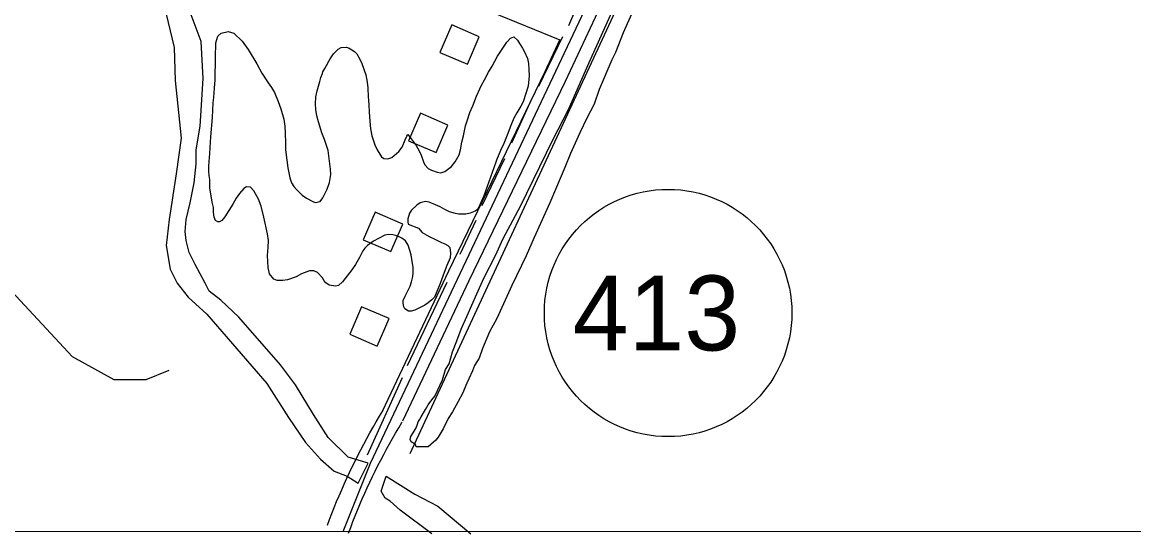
# Model space of a CAD drawing. Extents: x 3250478 to 3288318, y 788638 to 816472.
# Drawn here: x 3257033 to 3258515, y 794014 to 794702 of the extents above; entities that cross this region are included whole.
import ezdxf

# ---------------------------------------------------------------- set-up
doc = ezdxf.new("R2010")
doc.units = 0
for name, color, linetype in [('V-BLDG-OTLN', 7, 'Continuous'), ('V-GRID-FRAM', 7, 'Continuous'), ('V-ROAD-CNTR', 7, 'Continuous'), ('V-ROAD-IDEN', 7, 'Continuous'), ('V-SITE-VEGE', 7, 'Continuous'), ('V-TOPO-SHOR', 7, 'Continuous')]:
    doc.layers.add(name, color=color, linetype=linetype)

msp = doc.modelspace()

# ---------------------------------------------------------------- linework, layer by layer
at = {"layer": 'V-BLDG-OTLN'}
for points in [[(3257626.5, 794645.3), (3257642.3, 794682), (3257605.6, 794697.9), (3257589.8, 794661.2)], [(3257584.7, 794527.6), (3257600.6, 794564.3), (3257563.9, 794580.2), (3257548, 794543.4)], [(3257524.4, 794395.4), (3257540.3, 794432.1), (3257503.6, 794447.9), (3257487.7, 794411.2)], [(3257506.3, 794269.3), (3257522.2, 794306), (3257485.5, 794321.9), (3257469.6, 794285.2)]]:
    msp.add_lwpolyline(points, close=True, dxfattribs=at)
at = {"layer": 'V-GRID-FRAM'}
msp.add_lwpolyline([(3254649.6, 812209.1), (3286070.1, 812200), (3286072.7, 794013.5), (3254636.4, 794022.7), (3254649.6, 812209.1)], dxfattribs=at)
at = {"layer": 'V-ROAD-CNTR'}
for points in [[(3257460.7, 794021.9), (3257497.3, 794112.9), (3257860.4, 794882.3), (3257924.8, 795086.6), (3257932, 795269.1), (3257930.7, 796474.2), (3257808.6, 796519), (3257044, 796867.7), (3256342, 797271.9), (3255916.7, 797438.8), (3254738.6, 797696.6), (3254639.1, 797722.8)], [(3257540.5, 794169.6), (3257629, 794356.8), (3257757.1, 794622.8), (3257857.1, 794837), (3257911.9, 794967)], [(3257292.2, 794865.1), (3257749.7, 794677.9)], [(3257513.4, 794182.5), (3257601.9, 794369.7), (3257730, 794635.6), (3257749.7, 794677.9)], [(3257439.9, 794030.2), (3257442.8, 794038.1), (3257445.9, 794046), (3257449, 794053.9), (3257452.2, 794061.8), (3257455.5, 794069.6), (3257458.9, 794077.4), (3257462.3, 794085.2), (3257465.8, 794092.9), (3257469.4, 794100.6), (3257473, 794108.3), (3257476.8, 794115.9), (3257480.6, 794123.5), (3257484.4, 794131.1), (3257488.4, 794138.6), (3257492.4, 794146.1), (3257496.5, 794153.6), (3257500.7, 794161), (3257504.9, 794168.3), (3257509.2, 794175.7), (3257513.6, 794182.9), (3257514.1, 794183.8)], [(3257468, 794019.7), (3257470.9, 794027.4), (3257473.8, 794035.1), (3257476.9, 794042.7), (3257480, 794050.3), (3257483.1, 794057.9), (3257486.4, 794065.4), (3257489.7, 794072.9), (3257493.1, 794080.4), (3257496.5, 794087.9), (3257500.1, 794095.3), (3257503.7, 794102.6), (3257507.3, 794110), (3257511.1, 794117.3), (3257514.9, 794124.6), (3257518.8, 794131.8), (3257522.7, 794139), (3257526.8, 794146.1), (3257530.8, 794153.3), (3257535, 794160.3), (3257539.2, 794167.4), (3257539.7, 794168.2)]]:
    msp.add_lwpolyline(points, dxfattribs=at)
at = {"layer": 'V-ROAD-IDEN'}
msp.add_circle((3257894.1, 794313.5), 165, dxfattribs=at)
at = {"layer": 'V-SITE-VEGE'}
for points in [[(3257858.2, 794741.4), (3257834.4, 794687.4), (3257824, 794660.9), (3257819.2, 794651.1), (3257802.1, 794611.8), (3257795.4, 794592.1), (3257785.9, 794573.5), (3257776.3, 794553.8), (3257764, 794526.3), (3257756.3, 794507.6), (3257744, 794478.2), (3257736.4, 794460.5), (3257724, 794433), (3257715.4, 794414.3), (3257704.9, 794389.7), (3257685.8, 794350.4), (3257665.8, 794306.2), (3257656.2, 794288.5), (3257646.7, 794265.9), (3257642, 794253.2), (3257636.2, 794243.3), (3257633.4, 794236.4), (3257628.6, 794225.6), (3257625.8, 794219.7), (3257620.1, 794206), (3257614.3, 794195.2), (3257606.7, 794181.4), (3257600.9, 794172.5), (3257594.2, 794158.8), (3257587.5, 794147.9), (3257584.6, 794144), (3257577.8, 794138.1), (3257574, 794135.1), (3257558.3, 794134.9), (3257557.3, 794137.8), (3257551.4, 794141.7), (3257550.4, 794144.6), (3257551.3, 794148.5), (3257554.2, 794153.4), (3257558, 794160.3), (3257559.9, 794165.2)], [(3257559.9, 794165.2), (3257560.9, 794168.2), (3257562.8, 794171.1), (3257564.7, 794175), (3257570.5, 794184.9), (3257574.3, 794190.8), (3257579.1, 794197.7), (3257583, 794202.6), (3257593.5, 794224.2), (3257597.2, 794238), (3257602, 794245.8), (3257606.7, 794261.5), (3257612.4, 794276.3), (3257618.1, 794292), (3257625.7, 794308.7), (3257639, 794339.1), (3257648.6, 794359.8), (3257663.9, 794390.2), (3257674.4, 794412.8), (3257697.3, 794456.1), (3257740.3, 794544.6), (3257761.3, 794584.9), (3257788.9, 794647.8), (3257829.9, 794739.1)], [(3257287.9, 794454.3), (3257286.2, 794461.5), (3257283.3, 794480.4), (3257282.9, 794491.5), (3257282.3, 794497.1), (3257281.9, 794502.2), (3257281.9, 794509.5), (3257282.1, 794515.5), (3257283.3, 794526.3), (3257283.5, 794534.4), (3257284.4, 794548.7), (3257286.8, 794574.4), (3257287.6, 794593.9), (3257288.4, 794600.9), (3257289.3, 794613.3), (3257290, 794624.4), (3257290.5, 794654.6), (3257291.3, 794673.8), (3257293.9, 794683), (3257298.2, 794686.9), (3257307.6, 794689.1), (3257314.9, 794687.1), (3257326.4, 794676.1), (3257334.3, 794665.1), (3257345.6, 794645.8), (3257352.5, 794633.5), (3257361.1, 794620.4), (3257365.4, 794614.2), (3257369.3, 794607.8), (3257374, 794595.7), (3257377.7, 794585.7), (3257381.6, 794572), (3257383, 794562.8), (3257383.7, 794553.4), (3257383.9, 794540.2), (3257384.2, 794531.2), (3257385.7, 794517.2), (3257386.9, 794507.2), (3257389.8, 794493.8), (3257391.8, 794487.3), (3257395.1, 794482.2), (3257398.6, 794478.2), (3257406, 794470.7), (3257412.2, 794466.8), (3257421.5, 794461.7), (3257424.2, 794461), (3257430.1, 794462.4), (3257433.8, 794467), (3257439.6, 794478.7), (3257442.8, 794487.6), (3257444.3, 794498.5), (3257444.2, 794505.2), (3257440.9, 794530.3), (3257436.2, 794544.8), (3257432.6, 794553.9), (3257428.1, 794568.5), (3257425.8, 794576.5)], [(3257425.8, 794576.5), (3257424.6, 794584.9), (3257424, 794592.2), (3257424.5, 794601.9), (3257426.2, 794610), (3257429.9, 794622.2), (3257430.9, 794627.6), (3257433.3, 794633.1), (3257433.8, 794635.2), (3257436.4, 794639.9), (3257438.8, 794643.7), (3257441.7, 794649.6), (3257443.6, 794652.6), (3257448.1, 794659.4), (3257454.2, 794665.4), (3257458.3, 794667.7), (3257465.3, 794668.3), (3257469.1, 794666.7), (3257475.9, 794662.5), (3257479.1, 794659.3), (3257483.3, 794652), (3257485.8, 794646.4), (3257491.3, 794631.3), (3257492.8, 794621.6), (3257493.7, 794613.8), (3257494.1, 794601.4), (3257494.7, 794597.9), (3257496.1, 794574.7), (3257497.3, 794559.3), (3257499.3, 794549.9), (3257503, 794538), (3257506, 794531), (3257512.1, 794521.9), (3257515.1, 794519.8), (3257520.5, 794519), (3257525.8, 794521), (3257535.2, 794528.9), (3257539.7, 794534.9), (3257543.4, 794544.4), (3257545.8, 794549.6), (3257547.1, 794551.5), (3257551.5, 794545.9), (3257558.1, 794537), (3257561.6, 794530.6), (3257564.7, 794523.9), (3257567.8, 794515), (3257569.7, 794511.2), (3257574.3, 794506.4), (3257578.7, 794504.1), (3257586, 794501.4), (3257591.1, 794500.7), (3257596.5, 794502.4), (3257605.4, 794509), (3257610.2, 794515.2), (3257615.7, 794524.7), (3257617.5, 794531), (3257619.3, 794541.5), (3257621.4, 794549.9), (3257624.2, 794563.2), (3257626, 794569.9), (3257629.9, 794581.1), (3257633.9, 794590), (3257638.8, 794603), (3257645.2, 794617.4), (3257649.4, 794624.8), (3257654.7, 794634.8), (3257659.4, 794643), (3257666.6, 794656), (3257671.9, 794664.4), (3257679.1, 794675.1), (3257683.9, 794680.2), (3257688.4, 794681.9), (3257693.1, 794677.7), (3257695.8, 794673.1), (3257700.2, 794666.9), (3257702.7, 794662.1), (3257706.8, 794653.2), (3257708, 794646.5), (3257708.4, 794638.4), (3257709, 794630), (3257707.5, 794616), (3257701, 794595.4), (3257697.6, 794589.4), (3257692.3, 794580.7), (3257688.6, 794573.6), (3257683.6, 794561.4), (3257680.5, 794553), (3257675, 794539.5), (3257670.5, 794530.5), (3257665.2, 794517.2), (3257664.2, 794513.4), (3257648.5, 794469.8), (3257641.4, 794453.7), (3257640, 794451.8), (3257636.8, 794449.4), (3257630.1, 794446.6), (3257624.5, 794445.4), (3257615.3, 794445.3), (3257610.7, 794446.4), (3257602.5, 794448.7), (3257596.3, 794451.6)], [(3257596.3, 794451.6), (3257590.3, 794455), (3257584.1, 794457.9), (3257575.7, 794461.6), (3257570.8, 794462.1), (3257563.5, 794460.4), (3257559, 794457.4), (3257552, 794450.8), (3257549.4, 794446.7), (3257547.3, 794439.2), (3257547.1, 794435.1), (3257547.7, 794431.9), (3257561.5, 794426.9), (3257566.1, 794420.7), (3257575.4, 794415.7), (3257583, 794411.8), (3257592.2, 794407.5), (3257596.6, 794405.7), (3257600.4, 794403.6), (3257603.1, 794400.9), (3257604, 794393.4), (3257603.5, 794387.2), (3257599.1, 794376.8), (3257595.4, 794367.6), (3257590.4, 794352.7), (3257582.5, 794334.5), (3257579.3, 794331.2), (3257574.2, 794327.1), (3257569.7, 794324.1), (3257564.3, 794321.1), (3257556.3, 794317.2), (3257551.4, 794315.8), (3257547.9, 794315.8), (3257543.3, 794319), (3257541.6, 794321.6), (3257541, 794326.5), (3257541, 794330), (3257543.6, 794336), (3257550, 794349.5), (3257551.8, 794355), (3257553.9, 794362), (3257554.3, 794367.1), (3257554.3, 794374.7), (3257552.8, 794382), (3257551.6, 794391.1), (3257547.7, 794404.1), (3257543.9, 794409.7), (3257539.2, 794413.4), (3257536.5, 794414.7), (3257531.1, 794416.8), (3257527, 794417.9), (3257521.1, 794418.3), (3257516.5, 794417.5), (3257507.9, 794413), (3257501.5, 794409.2), (3257493.2, 794403.4), (3257489.7, 794399.9), (3257487, 794396.6), (3257482.6, 794387.4), (3257477.3, 794378.1), (3257472.5, 794371.1), (3257460, 794355.2), (3257454.6, 794350.3), (3257450.6, 794349.5), (3257442.2, 794350.5), (3257437.6, 794353.9), (3257435.7, 794356.6), (3257433.2, 794360.3), (3257426.6, 794367.6), (3257421.7, 794369.7), (3257416.1, 794369.6), (3257405.3, 794365.7), (3257398.1, 794361.8), (3257386.8, 794357.6), (3257380.6, 794356.8), (3257373, 794356.9), (3257368.4, 794358.8), (3257362.6, 794365.7), (3257360.7, 794374.1), (3257359.9, 794390), (3257360.9, 794400.8), (3257361.3, 794410.3), (3257360.1, 794419.2), (3257355.3, 794441.5), (3257351.6, 794456.1), (3257348, 794465.5), (3257341.9, 794476.5), (3257337.5, 794481.6), (3257331.9, 794481.8), (3257328.4, 794479.6), (3257322.8, 794473), (3257318.3, 794466.8), (3257313.8, 794458.6), (3257302.9, 794441.7), (3257299.2, 794437.1), (3257296, 794435.2), (3257293.8, 794435.1), (3257290.8, 794437), (3257288.9, 794441.3), (3257288.2, 794448), (3257287.9, 794454.3)]]:
    msp.add_lwpolyline(points, dxfattribs=at)
at = {"layer": 'V-TOPO-SHOR'}
for p, q in [((3257550.1, 794125.8), (3257865.1, 794804.7)), ((3257773.1, 794724.6), (3257761.1, 794696.8)), ((3257753.1, 794682.2), (3257721.3, 794615.8)), ((3257712, 794598.6), (3257685.4, 794540.2)), ((3257676.1, 794519), (3257645.6, 794456.6)), ((3257637.6, 794436.7), (3257616.4, 794391.6)), ((3257599.1, 794354.4), (3257546, 794243)), ((3257539.4, 794227.1), (3257492.9, 794123.6))]:
    msp.add_line(p, q, dxfattribs=at)
for points in [[(3255784.8, 794731.3), (3256161.4, 794811.4), (3256315.7, 794842.2), (3256463.8, 794836), (3256624.3, 794817.4), (3256716.9, 794774.2), (3256828, 794693.9), (3256895.9, 794619.8), (3256920.6, 794527.2), (3256951.4, 794434.6), (3257019.3, 794342), (3257099.5, 794255.6), (3257155, 794224.7), (3257198.2, 794224.7), (3257229.1, 794237)], [(3257222.4, 794723.5), (3257235.6, 794667.7), (3257236.9, 794623.9), (3257244.9, 794547), (3257238.2, 794499.2), (3257228.9, 794438.2), (3257224.9, 794403.7), (3257230.2, 794371.8), (3257239.5, 794353.2), (3257254.1, 794334.6), (3257279.3, 794312.1), (3257358.9, 794219.2), (3257388.1, 794174), (3257410.6, 794140.8), (3257430.5, 794118.3), (3257449.1, 794102.4), (3257466.3, 794095.7), (3257480.9, 794086.4), (3257494.2, 794113), (3257467.7, 794120.9), (3257441.1, 794147.5), (3257421.2, 794178), (3257397.4, 794217.8), (3257377.5, 794244.4), (3257321.8, 794308.1), (3257297.9, 794330.6), (3257282, 794342.6), (3257276.7, 794353.2), (3257263.4, 794378.4), (3257255.4, 794394.4), (3257251.5, 794410.3), (3257250.1, 794422.2), (3257251.5, 794438.1), (3257256.8, 794460.7), (3257262.1, 794487.2), (3257264.8, 794512.5), (3257264.8, 794531), (3257270.1, 794562.9), (3257274.1, 794626.6), (3257271.4, 794675.7), (3257258.2, 794711.5)], [(3257579.1, 794018.7), (3257536.7, 794050.6), (3257523.4, 794062.5), (3257516.8, 794066.5), (3257511.5, 794075.8), (3257518.1, 794095.7), (3257556.6, 794071.8), (3257587.1, 794055.9), (3257630.9, 794018.7)]]:
    msp.add_lwpolyline(points, dxfattribs=at)

# ---------------------------------------------------------------- texts
at = {"layer": 'V-ROAD-IDEN'}
msp.add_text('413', height=100, dxfattribs=at).set_placement((3257767, 794263.5))

doc.saveas('drawing.dxf')
